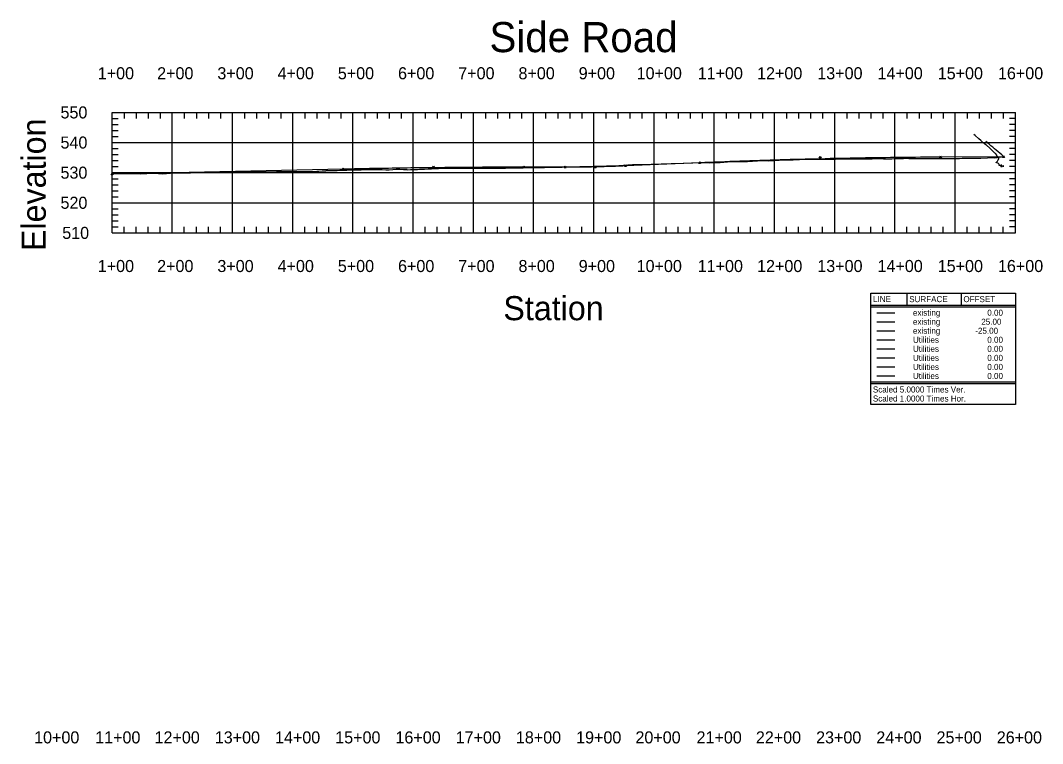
# Model space of a CAD drawing. Extents: x 708167 to 712470, y 374476 to 376945.
# Drawn here: x 708267 to 709965, y 375745 to 376945 of the extents above; entities that cross this region are included whole.
import ezdxf

# ---------------------------------------------------------------- set-up
doc = ezdxf.new("R2010")
doc.units = 0
for name, color, linetype in [('1', 7, 'Continuous'), ('10', 7, 'Continuous'), ('13', 7, 'Continuous'), ('48', 7, 'Continuous'), ('61', 7, 'Continuous'), ('63', 7, 'Continuous'), ('Default_Profile', 7, 'Continuous'), ('Existing', 7, 'Continuous')]:
    doc.layers.add(name, color=color, linetype=linetype)

msp = doc.modelspace()

# ---------------------------------------------------------------- linework, layer by layer
for points in [[(709395.4, 376710.7), (709396.9, 376707.7), (709393.9, 376707.7)], [(709595.4, 376719.1), (709596.9, 376716.1), (709593.9, 376716.1)], [(709795.4, 376720), (709796.9, 376717), (709793.9, 376717)], [(709899.8, 376720.5), (709901.3, 376717.5), (709898.3, 376717.5)], [(708803.4, 376700.1), (708804.9, 376697.1), (708801.9, 376697.1)], [(708953.4, 376703.3), (708954.9, 376700.3), (708951.9, 376700.3)], [(709103.4, 376703.3), (709104.9, 376700.3), (709101.9, 376700.3)], [(709172, 376703.3), (709173.5, 376700.3), (709170.5, 376700.3)], [(709222, 376703.3), (709223.5, 376700.3), (709220.5, 376700.3)], [(709272, 376705.4), (709273.5, 376702.4), (709270.5, 376702.4)], [(708419.5, 376691.9), (708421, 376688.9), (708418, 376688.9)]]:
    msp.add_lwpolyline(points, close=True)
at = {"layer": '10'}
msp.add_lwpolyline([(709899.8, 376703.6), (709899.5, 376703.8), (709899.5, 376702.5), (709899.4, 376701.7), (709897.5, 376703), (709896.9, 376703.5), (709895.6, 376703.6), (709895.5, 376703.6), (709895.3, 376703.6), (709895.1, 376703.6), (709894.8, 376703.7), (709894.2, 376703.9), (709893.3, 376704.1), (709892.5, 376704.3), (709892.5, 376705), (709892.4, 376705.6), (709892.3, 376706.9), (709891.6, 376707.7), (709889.5, 376708.8), (709888.8, 376709), (709888.5, 376709), (709888.3, 376709), (709887.4, 376708.8), (709887.5, 376708.9), (709887.7, 376709.1), (709888.3, 376709.6), (709888.4, 376709.8), (709889, 376710.4), (709889.2, 376710.7), (709889.7, 376711.3), (709889.9, 376711.6), (709890.4, 376712.5), (709891.1, 376713.6), (709891.8, 376715), (709892.3, 376715.8), (709891.9, 376716.4), (709889.3, 376719.7), (709889.2, 376720), (709889, 376720.3), (709888.6, 376721.1), (709886.9, 376723.6), (709886.4, 376724), (709885.6, 376724.7), (709884.5, 376725.7), (709882.2, 376727.8), (709876.9, 376733), (709871.3, 376737.9), (709870.6, 376738.5), (709868.4, 376740.3), (709862.1, 376745.5), (709858.9, 376748.5), (709852.7, 376753.9), (709850.4, 376755.8)], dxfattribs=at)
msp.add_lwpolyline([(709895.3, 376702.5), (709897.3, 376702.5), (709897.3, 376704.5), (709895.3, 376704.5)], close=True, dxfattribs=at)
at = {"layer": '13'}
msp.add_lwpolyline([(709899.8, 376719.3), (709898.6, 376720.4), (709897.2, 376721.6), (709893.9, 376724.4), (709891, 376726.7), (709887.7, 376729.5), (709884.7, 376732.1), (709881.9, 376734.4), (709879, 376736.9), (709875.9, 376739.6), (709873.8, 376741.4), (709872.9, 376742.1), (709870.3, 376744.1)], dxfattribs=at)
at = {"layer": '48'}
for p, q in [((709795.4, 376718.5), (709899.8, 376719)), ((708419.5, 376690.4), (708803.4, 376698.6)), ((709103.4, 376701.8), (709172, 376701.8)), ((709272, 376703.9), (709395.4, 376709.2))]:
    msp.add_line(p, q, dxfattribs=at)
for points in [[(709395.4, 376709.2), (709403.7, 376709.5), (709412.1, 376709.8), (709420.4, 376710.2), (709428.7, 376710.5), (709437.1, 376710.8), (709445.4, 376711.2), (709453.7, 376711.5), (709462.1, 376711.8), (709470.4, 376712.1), (709478.7, 376712.4), (709487.1, 376712.6), (709495.4, 376712.9), (709503.7, 376713.2), (709512.1, 376713.4), (709520.4, 376713.7), (709528.7, 376714), (709537.1, 376714.2), (709545.4, 376714.4), (709553.7, 376714.7), (709562.1, 376714.9), (709570.4, 376715.1), (709578.7, 376715.3), (709587.1, 376715.5), (709603.7, 376715.9), (709612.1, 376716.1), (709620.4, 376716.3), (709628.7, 376716.5), (709637.1, 376716.6), (709645.4, 376716.8), (709653.7, 376716.9), (709662.1, 376717.1), (709670.4, 376717.2), (709678.7, 376717.3), (709687.1, 376717.5), (709695.4, 376717.6), (709703.7, 376717.7), (709712.1, 376717.8), (709720.4, 376717.9), (709728.7, 376718), (709737.1, 376718.1), (709745.4, 376718.2), (709753.7, 376718.2), (709762.1, 376718.3), (709770.4, 376718.4), (709778.7, 376718.4), (709787.1, 376718.5), (709795.4, 376718.5)], [(708803.4, 376698.6), (708809.7, 376698.7), (708815.9, 376698.9), (708822.2, 376699), (708828.4, 376699.1), (708834.7, 376699.2), (708840.9, 376699.4), (708847.2, 376699.5), (708853.4, 376699.6), (708859.7, 376699.7), (708865.9, 376699.8), (708872.2, 376699.9), (708878.4, 376700), (708884.7, 376700.1), (708890.9, 376700.2), (708897.2, 376700.3), (708903.4, 376700.4), (708909.7, 376700.5), (708915.9, 376700.6), (708922.2, 376700.7), (708928.4, 376700.7), (708934.7, 376700.8), (708940.9, 376700.9), (708947.2, 376701), (708959.7, 376701.1), (708965.9, 376701.1), (708972.2, 376701.2), (708978.4, 376701.3), (708984.7, 376701.3), (708990.9, 376701.4), (708997.2, 376701.4), (709003.4, 376701.5), (709009.7, 376701.5), (709015.9, 376701.6), (709022.2, 376701.6), (709028.4, 376701.6), (709034.7, 376701.7), (709040.9, 376701.7), (709047.2, 376701.7), (709053.4, 376701.7), (709059.7, 376701.8), (709065.9, 376701.8), (709072.2, 376701.8), (709078.4, 376701.8), (709084.7, 376701.8), (709090.9, 376701.8), (709097.2, 376701.8), (709103.4, 376701.8)], [(709172, 376701.8), (709174, 376701.8), (709176.1, 376701.8), (709178.2, 376701.8), (709180.3, 376701.8), (709182.4, 376701.8), (709184.5, 376701.9), (709186.5, 376701.9), (709188.6, 376701.9), (709190.7, 376701.9), (709192.8, 376701.9), (709194.9, 376701.9), (709197, 376702), (709199, 376702), (709201.1, 376702), (709203.2, 376702), (709205.3, 376702.1), (709207.4, 376702.1), (709209.5, 376702.1), (709211.5, 376702.2), (709213.6, 376702.2), (709215.7, 376702.2), (709217.8, 376702.3), (709219.9, 376702.3), (709224, 376702.4), (709226.1, 376702.4), (709228.2, 376702.5), (709230.3, 376702.5), (709232.4, 376702.6), (709234.5, 376702.7), (709236.5, 376702.7), (709238.6, 376702.8), (709240.7, 376702.8), (709242.8, 376702.9), (709244.9, 376702.9), (709247, 376703), (709249, 376703.1), (709251.1, 376703.1), (709253.2, 376703.2), (709255.3, 376703.3), (709257.4, 376703.4), (709259.5, 376703.4), (709261.5, 376703.5), (709263.6, 376703.6), (709265.7, 376703.7), (709267.8, 376703.8), (709269.9, 376703.9), (709272, 376703.9)]]:
    msp.add_lwpolyline(points, dxfattribs=at)
at = {"layer": '61'}
for p, q in [((708419.5, 376792.3), (709919.5, 376792.3)), ((708419.5, 376592.3), (708419.5, 376792.3)), ((708419.5, 376782.3), (708429.5, 376782.3)), ((708439.5, 376792.3), (708439.5, 376782.3)), ((708459.5, 376792.3), (708459.5, 376782.3)), ((708479.5, 376792.3), (708479.5, 376782.3)), ((708499.5, 376792.3), (708499.5, 376782.3)), ((708519.5, 376592.3), (708519.5, 376792.3)), ((708539.5, 376792.3), (708539.5, 376782.3)), ((708559.5, 376792.3), (708559.5, 376782.3)), ((708579.5, 376792.3), (708579.5, 376782.3)), ((708599.5, 376792.3), (708599.5, 376782.3)), ((708619.5, 376592.3), (708619.5, 376792.3)), ((708639.5, 376792.3), (708639.5, 376782.3)), ((708659.5, 376792.3), (708659.5, 376782.3)), ((708679.5, 376792.3), (708679.5, 376782.3)), ((708699.5, 376792.3), (708699.5, 376782.3)), ((708719.5, 376592.3), (708719.5, 376792.3)), ((708739.5, 376792.3), (708739.5, 376782.3)), ((708759.5, 376792.3), (708759.5, 376782.3)), ((708779.5, 376792.3), (708779.5, 376782.3)), ((708799.5, 376792.3), (708799.5, 376782.3)), ((708819.5, 376592.3), (708819.5, 376792.3)), ((708839.5, 376792.3), (708839.5, 376782.3)), ((708859.5, 376792.3), (708859.5, 376782.3)), ((708879.5, 376792.3), (708879.5, 376782.3)), ((708899.5, 376792.3), (708899.5, 376782.3)), ((708919.5, 376592.3), (708919.5, 376792.3)), ((708939.5, 376792.3), (708939.5, 376782.3)), ((708959.5, 376792.3), (708959.5, 376782.3)), ((708979.5, 376792.3), (708979.5, 376782.3)), ((708999.5, 376792.3), (708999.5, 376782.3)), ((709019.5, 376592.3), (709019.5, 376792.3)), ((709039.5, 376792.3), (709039.5, 376782.3)), ((709059.5, 376792.3), (709059.5, 376782.3)), ((709079.5, 376792.3), (709079.5, 376782.3)), ((709099.5, 376792.3), (709099.5, 376782.3)), ((709119.5, 376592.3), (709119.5, 376792.3)), ((709139.5, 376792.3), (709139.5, 376782.3)), ((709159.5, 376792.3), (709159.5, 376782.3)), ((709179.5, 376792.3), (709179.5, 376782.3)), ((709199.5, 376792.3), (709199.5, 376782.3)), ((709219.5, 376592.3), (709219.5, 376792.3)), ((709239.5, 376792.3), (709239.5, 376782.3)), ((709259.5, 376792.3), (709259.5, 376782.3)), ((709279.5, 376792.3), (709279.5, 376782.3)), ((709299.5, 376792.3), (709299.5, 376782.3)), ((709319.5, 376592.3), (709319.5, 376792.3)), ((709339.5, 376792.3), (709339.5, 376782.3)), ((709359.5, 376792.3), (709359.5, 376782.3)), ((709379.5, 376792.3), (709379.5, 376782.3)), ((709399.5, 376792.3), (709399.5, 376782.3)), ((709419.5, 376592.3), (709419.5, 376792.3)), ((709439.5, 376792.3), (709439.5, 376782.3)), ((709459.5, 376792.3), (709459.5, 376782.3)), ((709479.5, 376792.3), (709479.5, 376782.3)), ((709499.5, 376792.3), (709499.5, 376782.3)), ((709519.5, 376592.3), (709519.5, 376792.3)), ((709539.5, 376792.3), (709539.5, 376782.3)), ((709559.5, 376792.3), (709559.5, 376782.3)), ((709579.5, 376792.3), (709579.5, 376782.3)), ((709599.5, 376792.3), (709599.5, 376782.3)), ((709619.5, 376592.3), (709619.5, 376792.3)), ((709639.5, 376792.3), (709639.5, 376782.3)), ((709659.5, 376792.3), (709659.5, 376782.3)), ((709679.5, 376792.3), (709679.5, 376782.3)), ((709699.5, 376792.3), (709699.5, 376782.3)), ((709719.5, 376592.3), (709719.5, 376792.3)), ((709739.5, 376792.3), (709739.5, 376782.3)), ((709759.5, 376792.3), (709759.5, 376782.3)), ((709779.5, 376792.3), (709779.5, 376782.3)), ((709799.5, 376792.3), (709799.5, 376782.3)), ((709819.5, 376592.3), (709819.5, 376792.3)), ((709839.5, 376792.3), (709839.5, 376782.3)), ((709859.5, 376792.3), (709859.5, 376782.3)), ((709879.5, 376792.3), (709879.5, 376782.3)), ((709899.5, 376792.3), (709899.5, 376782.3)), ((709919.5, 376782.3), (709909.5, 376782.3)), ((709919.5, 376592.3), (709919.5, 376792.3)), ((708419.5, 376772.3), (708429.5, 376772.3)), ((708419.5, 376762.3), (708429.5, 376762.3)), ((709919.5, 376772.3), (709909.5, 376772.3)), ((709919.5, 376762.3), (709909.5, 376762.3)), ((708419.5, 376752.3), (708429.5, 376752.3)), ((709919.5, 376752.3), (709909.5, 376752.3)), ((708419.5, 376742.3), (709919.5, 376742.3)), ((708419.5, 376732.3), (708429.5, 376732.3)), ((709919.5, 376732.3), (709909.5, 376732.3)), ((708419.5, 376722.3), (708429.5, 376722.3)), ((708419.5, 376712.3), (708429.5, 376712.3)), ((709919.5, 376722.3), (709909.5, 376722.3)), ((709919.5, 376712.3), (709909.5, 376712.3)), ((708419.5, 376702.3), (708429.5, 376702.3)), ((709919.5, 376702.3), (709909.5, 376702.3)), ((708419.5, 376692.3), (709919.5, 376692.3)), ((708419.5, 376682.3), (708429.5, 376682.3)), ((709919.5, 376682.3), (709909.5, 376682.3)), ((708419.5, 376672.3), (708429.5, 376672.3)), ((708419.5, 376662.3), (708429.5, 376662.3)), ((709919.5, 376672.3), (709909.5, 376672.3)), ((709919.5, 376662.3), (709909.5, 376662.3)), ((708419.5, 376652.3), (708429.5, 376652.3)), ((708419.5, 376642.3), (709919.5, 376642.3)), ((709919.5, 376652.3), (709909.5, 376652.3)), ((708419.5, 376632.3), (708429.5, 376632.3)), ((709919.5, 376632.3), (709909.5, 376632.3)), ((708419.5, 376622.3), (708429.5, 376622.3)), ((708419.5, 376612.3), (708429.5, 376612.3)), ((709919.5, 376622.3), (709909.5, 376622.3)), ((709919.5, 376612.3), (709909.5, 376612.3)), ((708419.5, 376602.3), (708429.5, 376602.3)), ((708419.5, 376592.3), (709919.5, 376592.3)), ((708439.5, 376592.3), (708439.5, 376602.3)), ((708459.5, 376592.3), (708459.5, 376602.3)), ((708479.5, 376592.3), (708479.5, 376602.3)), ((708499.5, 376592.3), (708499.5, 376602.3)), ((708539.5, 376592.3), (708539.5, 376602.3)), ((708559.5, 376592.3), (708559.5, 376602.3)), ((708579.5, 376592.3), (708579.5, 376602.3)), ((708599.5, 376592.3), (708599.5, 376602.3)), ((708639.5, 376592.3), (708639.5, 376602.3)), ((708659.5, 376592.3), (708659.5, 376602.3)), ((708679.5, 376592.3), (708679.5, 376602.3)), ((708699.5, 376592.3), (708699.5, 376602.3)), ((708739.5, 376592.3), (708739.5, 376602.3)), ((708759.5, 376592.3), (708759.5, 376602.3)), ((708779.5, 376592.3), (708779.5, 376602.3)), ((708799.5, 376592.3), (708799.5, 376602.3)), ((708839.5, 376592.3), (708839.5, 376602.3)), ((708859.5, 376592.3), (708859.5, 376602.3)), ((708879.5, 376592.3), (708879.5, 376602.3)), ((708899.5, 376592.3), (708899.5, 376602.3)), ((708939.5, 376592.3), (708939.5, 376602.3)), ((708959.5, 376592.3), (708959.5, 376602.3)), ((708979.5, 376592.3), (708979.5, 376602.3)), ((708999.5, 376592.3), (708999.5, 376602.3)), ((709039.5, 376592.3), (709039.5, 376602.3)), ((709059.5, 376592.3), (709059.5, 376602.3)), ((709079.5, 376592.3), (709079.5, 376602.3)), ((709099.5, 376592.3), (709099.5, 376602.3)), ((709139.5, 376592.3), (709139.5, 376602.3)), ((709159.5, 376592.3), (709159.5, 376602.3)), ((709179.5, 376592.3), (709179.5, 376602.3)), ((709199.5, 376592.3), (709199.5, 376602.3)), ((709239.5, 376592.3), (709239.5, 376602.3)), ((709259.5, 376592.3), (709259.5, 376602.3)), ((709279.5, 376592.3), (709279.5, 376602.3)), ((709299.5, 376592.3), (709299.5, 376602.3)), ((709339.5, 376592.3), (709339.5, 376602.3)), ((709359.5, 376592.3), (709359.5, 376602.3)), ((709379.5, 376592.3), (709379.5, 376602.3)), ((709399.5, 376592.3), (709399.5, 376602.3)), ((709439.5, 376592.3), (709439.5, 376602.3)), ((709459.5, 376592.3), (709459.5, 376602.3)), ((709479.5, 376592.3), (709479.5, 376602.3)), ((709499.5, 376592.3), (709499.5, 376602.3)), ((709539.5, 376592.3), (709539.5, 376602.3)), ((709559.5, 376592.3), (709559.5, 376602.3)), ((709579.5, 376592.3), (709579.5, 376602.3)), ((709599.5, 376592.3), (709599.5, 376602.3)), ((709639.5, 376592.3), (709639.5, 376602.3)), ((709659.5, 376592.3), (709659.5, 376602.3)), ((709679.5, 376592.3), (709679.5, 376602.3)), ((709699.5, 376592.3), (709699.5, 376602.3)), ((709739.5, 376592.3), (709739.5, 376602.3)), ((709759.5, 376592.3), (709759.5, 376602.3)), ((709779.5, 376592.3), (709779.5, 376602.3)), ((709799.5, 376592.3), (709799.5, 376602.3)), ((709839.5, 376592.3), (709839.5, 376602.3)), ((709859.5, 376592.3), (709859.5, 376602.3)), ((709879.5, 376592.3), (709879.5, 376602.3)), ((709899.5, 376592.3), (709899.5, 376602.3)), ((709919.5, 376602.3), (709909.5, 376602.3)), ((709739.5, 376492.3), (709739.5, 376472.3)), ((709829.5, 376492.3), (709829.5, 376472.3)), ((709679.5, 376472.3), (709919.5, 376472.3)), ((709679.5, 376469.8), (709919.5, 376469.8)), ((709679.5, 376344.8), (709919.5, 376344.8)), ((709679.5, 376342.3), (709919.5, 376342.3))]:
    msp.add_line(p, q, dxfattribs=at)
msp.add_lwpolyline([(709679.5, 376492.3), (709919.5, 376492.3), (709919.5, 376307.3), (709679.5, 376307.3)], close=True, dxfattribs=at)
at = {"layer": '63'}
for p, q in [((709689.5, 376444.8), (709719.5, 376444.8)), ((709689.5, 376429.8), (709719.5, 376429.8))]:
    msp.add_line(p, q, dxfattribs=at)
at = {"layer": 'Default_Profile'}
for p, q in [((709689.5, 376414.8), (709719.5, 376414.8)), ((709689.5, 376399.8), (709719.5, 376399.8)), ((709689.5, 376384.8), (709719.5, 376384.8)), ((709689.5, 376369.8), (709719.5, 376369.8)), ((709689.5, 376354.8), (709719.5, 376354.8))]:
    msp.add_line(p, q, dxfattribs=at)
at = {"layer": 'Existing'}
msp.add_line((709689.5, 376459.8), (709719.5, 376459.8), dxfattribs=at)
msp.add_lwpolyline([(708419.5, 376690.4), (708452.7, 376690.9), (708452.7, 376690.9), (708466, 376690.4), (708488.6, 376691.6), (708489.7, 376691.6), (708504.1, 376690.5), (708522.5, 376691.8), (708523, 376691.8), (708549.8, 376691.8), (708561.5, 376692.8), (708600, 376693.4), (708614.2, 376692.8), (708623.2, 376693), (708644.7, 376693.6), (708648.3, 376693.8), (708651.3, 376693.8), (708663.1, 376694), (708663.2, 376694), (708669, 376694), (708674.8, 376693.9), (708680.4, 376693.9), (708680.7, 376693.9), (708682.8, 376693.8), (708684.3, 376693.8), (708685.8, 376693.8), (708686.5, 376693.8), (708692.4, 376694), (708698.2, 376694.1), (708704.1, 376694.3), (708706.5, 376694.3), (708710, 376694.3), (708715.6, 376694.2), (708715.8, 376694.2), (708721.7, 376694.3), (708726.2, 376694.4), (708727.5, 376694.4), (708727.6, 376694.4), (708729, 376694.4), (708730.4, 376694.4), (708733.4, 376694.4), (708739.2, 376694.3), (708745.1, 376694.2), (708750.9, 376694.2), (708751, 376694.2), (708754.8, 376694.3), (708756.8, 376694.4), (708759.6, 376694.5), (708762.7, 376694.7), (708768.5, 376695.1), (708774.4, 376695.5), (708775.1, 376695.6), (708775.3, 376695.6), (708776.9, 376695.6), (708780.2, 376695.8), (708786.1, 376695.9), (708791.9, 376696.1), (708793.5, 376696.1), (708797.8, 376696.3), (708803.7, 376696.4), (708809.5, 376696.6), (708814.4, 376696.7), (708815.4, 376696.7), (708815.5, 376696.7), (708816.6, 376696.7), (708817.5, 376696.7), (708821.2, 376696.9), (708827.1, 376697), (708832.9, 376697.2), (708838.8, 376697.4), (708843.4, 376697.5), (708844.7, 376697.5), (708850.5, 376697.6), (708851.2, 376697.6), (708851.7, 376697.6), (708856.4, 376697.6), (708862.2, 376697.4), (708868.1, 376697.3), (708873.9, 376697.2), (708878.9, 376697.1), (708879.8, 376697.1), (708885.7, 376697.6), (708891.5, 376698.1), (708892.1, 376698.1), (708892.4, 376698.1), (708892.6, 376698.1), (708892.9, 376698.1), (708897.4, 376697.9), (708903.2, 376697.6), (708909.1, 376697.3), (708909.7, 376697.2), (708914.9, 376697.3), (708915.3, 376697.4), (708920.4, 376697.5), (708920.8, 376697.5), (708925.4, 376697.7), (708926.7, 376697.7), (708930.1, 376697.8), (708932.5, 376697.9), (708938.4, 376698.2), (708944.2, 376698.5), (708950.1, 376698.8), (708955.9, 376699), (708961.8, 376699.3), (708967.7, 376699.6), (708969.1, 376699.6), (708972.6, 376699.7), (708973.5, 376699.8), (708975.1, 376699.8), (708979.4, 376699.9), (708983.4, 376700), (708985.2, 376700), (708988.5, 376700), (708991.1, 376700), (708996.9, 376700), (709002.8, 376700), (709008.6, 376700), (709014.5, 376700), (709016.8, 376700), (709020.4, 376700), (709026.2, 376699.9), (709026.5, 376699.9), (709032.1, 376700), (709033.1, 376700), (709034, 376700), (709034.9, 376700), (709035.8, 376700), (709037.9, 376700), (709043.8, 376700), (709046.4, 376699.9), (709049.6, 376699.9), (709051.3, 376699.8), (709055.5, 376699.9), (709056.5, 376699.9), (709061.4, 376699.8), (709066, 376699.7), (709067.2, 376699.7), (709067.2, 376699.7), (709068.5, 376699.7), (709073.1, 376699.9), (709078.9, 376700.1), (709080.8, 376700.1), (709084.8, 376700.2), (709085.7, 376700.2), (709090.6, 376700.2), (709093.6, 376700.3), (709096.5, 376700.3), (709098.2, 376700.3), (709102.4, 376700.4), (709108.2, 376700.6), (709114.1, 376700.8), (709115, 376700.8), (709116.2, 376700.8), (709117, 376700.8), (709117.8, 376700.8), (709119.9, 376700.9), (709125.8, 376700.9), (709128.9, 376701), (709131.6, 376701), (709137.5, 376701.1), (709137.7, 376701.2), (709143.4, 376701.3), (709146.9, 376701.4), (709149.2, 376701.4), (709155.1, 376701.4), (709160.8, 376701.4), (709160.9, 376701.4), (709162.3, 376701.4), (709164, 376701.4), (709166.8, 376701.5), (709172.6, 376701.7), (709178.4, 376701.9), (709178.5, 376701.9), (709184.4, 376702), (709185.2, 376702), (709190.2, 376702.1), (709191.6, 376702.1), (709196.1, 376702.4), (709201.5, 376702.7), (709201.6, 376702.7), (709201.7, 376702.7), (709212.1, 376702.6), (709219.3, 376702.8), (709239.3, 376703.3), (709241.2, 376703.4), (709261.1, 376704.4), (709283.6, 376706), (709297.9, 376706), (709315, 376706.3), (709347.9, 376707.4), (709348.1, 376707.4), (709348.3, 376707.4), (709369.1, 376707.8), (709399.2, 376708.9), (709400.6, 376709), (709411.2, 376708.8), (709429.3, 376709.3), (709447.5, 376710.6), (709449.7, 376710.7), (709474.6, 376710.9), (709499.8, 376712.2), (709510, 376712), (709527.4, 376712.8), (709550.1, 376713.6), (709550.6, 376713.6), (709560.8, 376713.9), (709593.6, 376714.7), (709594.8, 376714.8), (709602.3, 376714.8), (709606.9, 376714.8), (709611.6, 376714.8), (709614.5, 376714.8), (709616.3, 376714.8), (709621, 376714.9), (709625.6, 376715), (709630.3, 376715), (709632.9, 376715.1), (709635, 376715.1), (709639.7, 376715.2), (709643.9, 376715.4), (709644.3, 376715.4), (709645.7, 376715.4), (709649, 376715.4), (709653.7, 376715.4), (709658.3, 376715.4), (709663, 376715.4), (709667.7, 376715.4), (709671.7, 376715.4), (709672.4, 376715.4), (709677, 376715.5), (709681.7, 376715.5), (709686.4, 376715.6), (709688.4, 376715.6), (709691.1, 376715.6), (709691.3, 376715.6), (709695.7, 376715.6), (709700.4, 376715.5), (709705.1, 376715.5), (709707.6, 376715.5), (709709.8, 376715.4), (709710.5, 376715.4), (709714.4, 376715.5), (709719.1, 376715.7), (709723.8, 376715.8), (709728.4, 376715.9), (709733.1, 376716), (709733.6, 376716), (709737.1, 376716.1), (709737.8, 376716.1), (709742.5, 376715.9), (709747.1, 376715.8), (709747.9, 376715.8), (709751.8, 376715.8), (709756.5, 376715.8), (709761.2, 376715.8), (709765.8, 376715.8), (709770.5, 376715.8), (709775, 376715.8), (709775.2, 376715.8), (709779.8, 376715.9), (709780.2, 376715.9), (709784.5, 376715.9), (709789.2, 376716), (709790.5, 376716), (709793.9, 376715.9), (709798.5, 376715.9), (709802.6, 376715.9), (709803.2, 376715.9), (709807.9, 376715.9), (709812.6, 376715.9), (709817.2, 376715.9), (709820.4, 376716), (709821.9, 376716), (709822.6, 376716), (709826.6, 376716), (709831.2, 376716.1), (709835.9, 376716.1), (709839, 376716.2), (709840.6, 376716.2), (709845.3, 376716.2), (709849.9, 376716.3), (709862.1, 376716.4), (709873.5, 376716.7), (709876.9, 376717.2), (709881, 376717.5), (709885.1, 376717), (709899.8, 376719)], dxfattribs=at)

# ---------------------------------------------------------------- texts
at = {"layer": '1'}
for s, height, p in [('Side Road', 50, (709046.3, 376892.3)), ('Station', 40, (709069.3, 376447.3)), (' LINE ', 10, (709679.5, 376477.3)), (' SURFACE ', 10, (709739.5, 376477.3)), (' OFFSET ', 10, (709829.5, 376477.3)), ('existing', 10, (709749.5, 376454.8)), ('0.00', 10, (709872.9, 376454.8)), ('existing', 10, (709749.5, 376439.8)), ('25.00', 10, (709862.9, 376439.8)), ('existing', 10, (709749.5, 376424.8)), ('-25.00', 10, (709852.9, 376424.8)), ('Utilities', 10, (709749.5, 376409.8)), ('Utilities', 10, (709749.5, 376394.8)), ('0.00', 10, (709872.9, 376409.8)), ('0.00', 10, (709872.9, 376394.8)), ('Utilities', 10, (709749.5, 376379.8)), ('0.00', 10, (709872.9, 376379.8)), ('Utilities', 10, (709749.5, 376364.8)), ('0.00', 10, (709872.9, 376364.8)), ('Utilities', 10, (709749.5, 376349.8)), ('0.00', 10, (709872.9, 376349.8)), ('Scaled 5.0000 Times Ver.', 10, (709682.9, 376327.3)), ('Scaled 1.0000 Times Hor.', 10, (709682.9, 376312.3))]:
    msp.add_text(s, height=height, dxfattribs=at).set_placement(p)
msp.add_text('Elevation', height=40, rotation=90, dxfattribs=at).set_placement((708309.5, 376562.1))
at = {"layer": '61'}
for s, p in [('1+00', (708395.8, 376847.3)), ('2+00', (708494.4, 376847.3)), ('3+00', (708594.4, 376847.3)), ('4+00', (708694.4, 376847.3)), ('5+00', (708794.4, 376847.3)), ('6+00', (708894.4, 376847.3)), ('7+00', (708994.4, 376847.3)), ('8+00', (709094.4, 376847.3)), ('9+00', (709194.4, 376847.3)), ('10+00', (709290.6, 376847.3)), ('11+00', (709392, 376847.3)), ('12+00', (709490.6, 376847.3)), ('13+00', (709590.6, 376847.3)), ('14+00', (709690.6, 376847.3)), ('15+00', (709790.6, 376847.3)), ('16+00', (709890.6, 376847.3)), ('550', (708333.9, 376782.3)), ('550', (708333.9, 376782.3)), ('540', (708333.9, 376732.3)), ('530', (708333.9, 376682.3)), ('520', (708333.9, 376632.3)), ('510', (708336.8, 376582.3)), ('1+00', (708395.8, 376527.3)), ('2+00', (708494.4, 376527.3)), ('3+00', (708594.4, 376527.3)), ('4+00', (708694.4, 376527.3)), ('5+00', (708794.4, 376527.3)), ('6+00', (708894.4, 376527.3)), ('7+00', (708994.4, 376527.3)), ('8+00', (709094.4, 376527.3)), ('9+00', (709194.4, 376527.3)), ('10+00', (709290.6, 376527.3)), ('11+00', (709392, 376527.3)), ('12+00', (709490.6, 376527.3)), ('13+00', (709590.6, 376527.3)), ('14+00', (709690.6, 376527.3)), ('15+00', (709790.6, 376527.3)), ('16+00', (709890.6, 376527.3)), ('10+00', (708290.1, 375744.8)), ('11+00', (708391.5, 375744.8)), ('12+00', (708490.1, 375744.8)), ('13+00', (708590.1, 375744.8)), ('14+00', (708690.1, 375744.8)), ('15+00', (708790.1, 375744.8)), ('16+00', (708890.1, 375744.8)), ('17+00', (708990.1, 375744.8)), ('18+00', (709090.1, 375744.8)), ('19+00', (709190.1, 375744.8)), ('20+00', (709288.6, 375744.8)), ('21+00', (709390.1, 375744.8)), ('22+00', (709488.6, 375744.8)), ('23+00', (709588.6, 375744.8)), ('24+00', (709688.6, 375744.8)), ('25+00', (709788.6, 375744.8)), ('26+00', (709888.6, 375744.8))]:
    msp.add_text(s, height=20, dxfattribs=at).set_placement(p)

doc.saveas('drawing.dxf')
